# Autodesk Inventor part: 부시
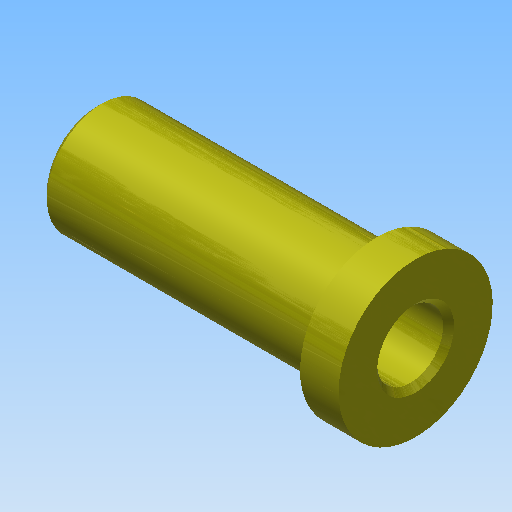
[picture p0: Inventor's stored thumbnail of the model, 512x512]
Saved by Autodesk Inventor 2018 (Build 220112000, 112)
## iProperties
Created: 2016-11
Part Number: 부시
Material: 강철, 연강
Document SubType Name: Modeling
Designer: mduedu
Density: 1 g/cm^3
Appearance: 노란색
Author: mduedu
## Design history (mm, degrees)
sketch "스케치1"
  geometry: L1 (0, 0)-(58, 0); L2 (58, 0)-(58, 14); L3 (58, 14)-(51, 14); L4 (51, 14)-(51, 10); L5 (51, 10)-(0, 10); L6 (0, 10)-(0, 0)
  constraints: 12 end point, 3 parallel, 2 perpendicular, 1 horizontal
  dimensions: "d0" = 58 distance of L1.start L1.end; "d1" = 7 distance of L2.end L3.end; "d2" = 28 diameter of L3 L1; "d3" = 20 diameter of L5 L1
revolve "회전1" sketch "스케치1" stored, may be unused: angle "d4" = 90 deg
hole "구멍1" diameter "d7" = 12; stored, may be unused: countersink angle "d11" = 90 deg, drill point angle "d13" = 118 deg; dims "d5" = 10, "d6" = 10, "d8" = 6, "d9" = 4, "d10" = 2, "d12" = 8
chamfer "모따기1" distance "d14" = 1; stored, may be unused: second distance "d15" = 2, angle "d16" = 45 deg
node "솔리드1"
